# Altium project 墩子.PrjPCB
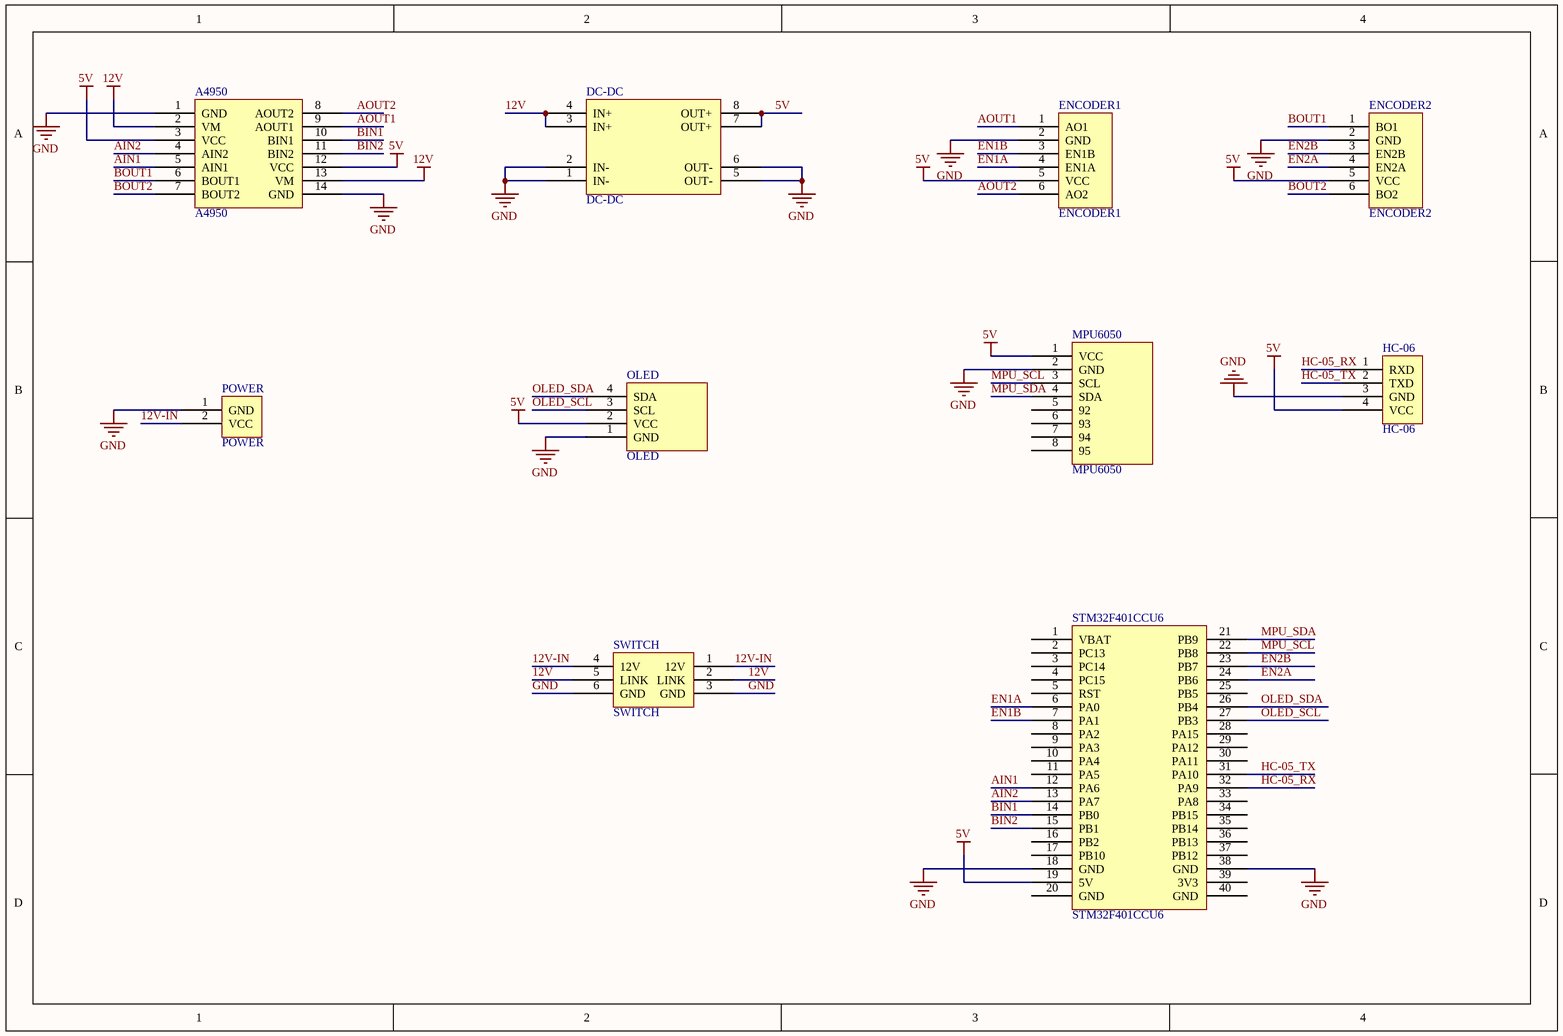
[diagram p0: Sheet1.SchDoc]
1 sheet, 10 parts. Net scope: global (net labels, ports and power ports of the same name join across sheets).
Board file: 平衡车.PcbDoc

## Sheet Sheet1.SchDoc
size A4

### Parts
A4950  A4950  [A4950]
DC-DC  DC-DC  [DC-DC]
ENCODER1  ENCODER1  [ENCODER1]
ENCODER2  ENCODER2  [ENCODER2]
HC-06  HC-06  [HC-06]
MPU6050  MPU6050  [MPU6050]
OLED  OLED  [OLED]
POWER  POWER  [POWER]
STM32F401CCU6  STM32F401CCU6  [STM32F401CCU6]
SWITCH  SWITCH  [SIWITCH]

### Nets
5V: A4950.3(VCC) A4950.12(VCC) DC-DC.7(OUT+) DC-DC.8(OUT+) ENCODER1.5(VCC) ENCODER2.5(VCC) HC-06.4(VCC) MPU6050.1(VCC) OLED.2(VCC) STM32F401CCU6.19(5V)
12V: A4950.2(VM) A4950.13(VM) DC-DC.3(IN+) DC-DC.4(IN+) SWITCH.2(LINK) SWITCH.5(LINK)
GND: A4950.1(GND) A4950.14(GND) DC-DC.1(IN-) DC-DC.2(IN-) DC-DC.5(OUT-) DC-DC.6(OUT-) ENCODER1.2(GND) ENCODER2.2(GND) HC-06.3(GND) MPU6050.2(GND) OLED.1(GND) POWER.1(GND) STM32F401CCU6.18(GND) STM32F401CCU6.38(GND) SWITCH.3(GND) SWITCH.6(GND)
12V-IN: POWER.2(VCC) SWITCH.1(12V) SWITCH.4(12V)
AIN1: A4950.5(AIN1) STM32F401CCU6.12(PA6)
AIN2: A4950.4(AIN2) STM32F401CCU6.13(PA7)
AOUT1: A4950.9(AOUT1) ENCODER1.1(AO1)
AOUT2: A4950.8(AOUT2) ENCODER1.6(AO2)
BIN1: A4950.10(BIN1) STM32F401CCU6.14(PB0)
BIN2: A4950.11(BIN2) STM32F401CCU6.15(PB1)
BOUT1: A4950.6(BOUT1) ENCODER2.1(BO1)
BOUT2: A4950.7(BOUT2) ENCODER2.6(BO2)
EN1A: ENCODER1.4(EN1A) STM32F401CCU6.6(PA0)
EN1B: ENCODER1.3(EN1B) STM32F401CCU6.7(PA1)
EN2A: ENCODER2.4(EN2A) STM32F401CCU6.24(PB6)
EN2B: ENCODER2.3(EN2B) STM32F401CCU6.23(PB7)
HC-05_RX: HC-06.1(RXD) STM32F401CCU6.32(PA9)
HC-05_TX: HC-06.2(TXD) STM32F401CCU6.31(PA10)
MPU_SCL: MPU6050.3(SCL) STM32F401CCU6.22(PB8)
MPU_SDA: MPU6050.4(SDA) STM32F401CCU6.21(PB9)
OLED_SCL: OLED.3(SCL) STM32F401CCU6.27(PB3)
OLED_SDA: OLED.4(SDA) STM32F401CCU6.26(PB4)

Not connected (* = marked no-connect by the designer): MPU6050 5(92) 6(93) 7(94) 8(95); STM32F401CCU6 1(VBAT) 2(PC13) 3(PC14) 4(PC15) 5(RST) 8(PA2) 9(PA3) 10(PA4) 11(PA5) 16(PB2) 17(PB10) 20(GND) 25(PB5) 28(PA15) 29(PA12) 30(PA11) 33(PA8) 34(PB15) 35(PB14) 36(PB13) 37(PB12) 39(3V3) 40(GND)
